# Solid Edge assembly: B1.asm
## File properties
Author: edge
Template: Jis Assembly.asm
Last saved by: edge
Revision: 9
Application: Solid Edge
Username: edge
文書内容のタイプ: 1
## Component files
C1.par
C2.par
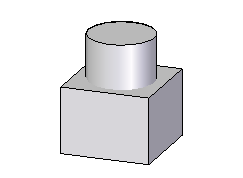
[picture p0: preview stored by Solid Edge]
